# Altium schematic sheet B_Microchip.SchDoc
size B; CompanyName: Microchip Technology Inc.; Organization: Microchip Technology; Address1: 2355 West Chandler Blvd.; Address2: Chandler, AZ  85224; Address4: USA; DocumentNumber: 1; SheetNumber: 1; SheetTotal: 1; SheetTitle: 3p3V_SAM9X6_SDRAM_MIC23201
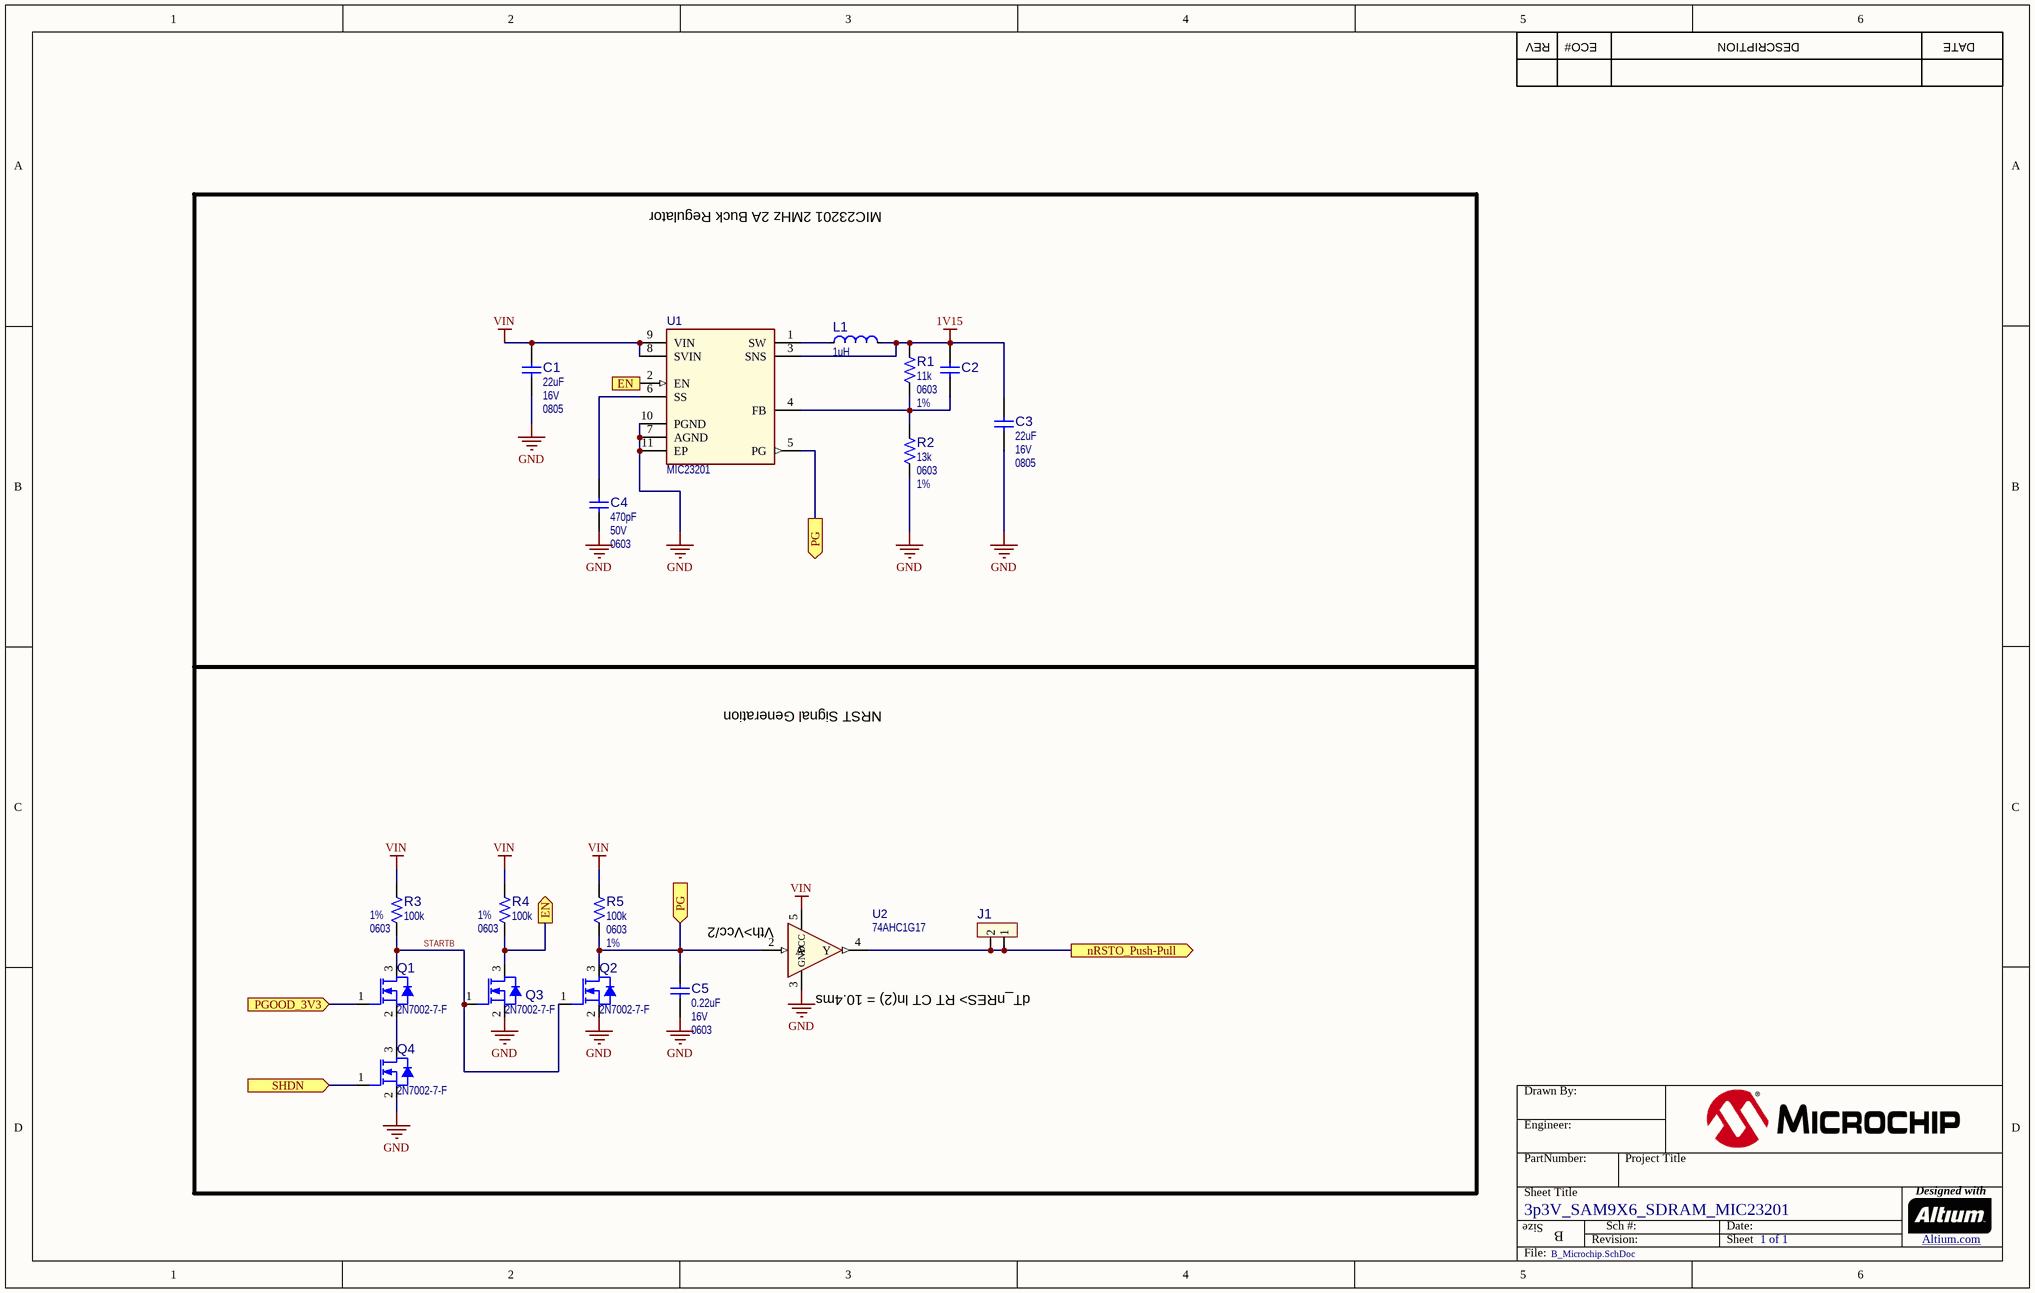
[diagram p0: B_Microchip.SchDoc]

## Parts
?  (no value)  (graphical)
C1  value 22uF  Voltage: 16V  Package: 0805  [CAP_C_0805]  (hidden comment: Capacitor NP)
C2  Capacitor NP  [CAP_C_0603]  (value not drawn)
C3  value 22uF  Voltage: 16V  Package: 0805  [CAP_C_0805]  (hidden comment: Capacitor NP)
C4  value 470pF  Voltage: 50V  Package: 0603  [CAP_C_0603]  (hidden comment: Capacitor NP)
C5  value 0.22uF  Voltage: 16V  Package: 0603  [CAP_C_0603]  (hidden comment: Capacitor NP)
J1  Header 1x2  [HDR_M_2.54_1x2]  (value not drawn)
L1  value 1uH  [IND_C_2520]  (hidden comment: Inductor)
Q1  value 2N7002-7-F  [SOT-23-3]  (hidden comment: Transistor MOS-N GSD)
Q2  value 2N7002-7-F  [SOT-23-3]  (hidden comment: Transistor MOS-N GSD)
Q3  value 2N7002-7-F  [SOT-23-3]  (hidden comment: Transistor MOS-N GSD)
Q4  value 2N7002-7-F  [SOT-23-3]  (hidden comment: Transistor MOS-N GSD)
R1  value 11k  Package: 0603  Tolerance: 1%  [RES_C_0603]  (hidden comment: Resistor)
R2  value 13k  Package: 0603  Tolerance: 1%  [RES_C_0603]  (hidden comment: Resistor)
R3  value 100k  Package: 0603  Tolerance: 1%  [RES_C_0603]  (hidden comment: Resistor)
R4  value 100k  Package: 0603  Tolerance: 1%  [RES_C_0603]  (hidden comment: Resistor)
R5  value 100k  Package: 0603  Tolerance: 1%  [RES_C_0603]  (hidden comment: Resistor)
U1  value MIC23201  [MLF-10_3x3_1.6X2.5]  (hidden comment: MIC23201 MLF-10)
U2  value 74AHC1G17  [SC-70-5]  (hidden comment: 74AHC1G17 TSSOP5)

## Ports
EN (in), EN (out), nRSTO_Push-Pull (out), PG (in), PG (out), PGOOD_3V3 (in), SHDN (in)

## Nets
1V15: C2.2 C3.2 L1.2(F) R1.2 U1.3(SNS)
GND: C1.1 C3.1 C4.1 C5.1 Q2.2(S) Q3.2(S) Q4.2(S) R2.1 U1.7(AGND) U1.10(PGND) U1.11(EP) U2.3(GND)
VIN: C1.2 R3.1 R4.1 R5.2 U1.8(SVIN) U1.9(VIN) U2.5(VCC)
EN: Q3.3(D) R4.2 U1.2(EN) ; port EN
nRSTO_Push-Pull: J1.1 J1.2 U2.4(Y) ; port nRSTO_Push-Pull
PG: C5.2 Q2.3(D) R5.1 U1.5(PG) U2.2(A) ; port PG
PGOOD_3V3: Q1.1(G) ; port PGOOD_3V3
SHDN: Q4.1(G) ; port SHDN
STARTB: Q1.3(D) Q2.1(G) Q3.1(G) R3.2
NetC2_1: C2.1 R1.1 R2.2 U1.4(FB)
NetC4_2: C4.2 U1.6(SS)
NetL1_1: L1.1(S) U1.1(SW)
NetQ1_2: Q1.2(S) Q4.3(D)

Not connected (* = marked no-connect by the designer): U2 1(NC)

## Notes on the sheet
- REV
- ECO#
- DESCRIPTION
- DATE
- MIC23201 2MHz 2A Buck Regulator
- NRST Signal Generation
- (near U2) Vth>Vcc/2
- (near U2) dT_nRES> RT CT ln(2) = 10.4ms

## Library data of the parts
? = Title Block B
C1 C3 = CAP0627: Capacitor; Manufacturer 1: TDK; Manufacturer Part Number 1: C2012X5R1C226K; Description_: CAP CER 22uF 16V 10% X5R SMD 0805; Dev Tools Status: Production; Tolerance: 10%; Temperature Coeffcient: X5R; Type: Ceramic; Populated: Yes
C2 = CAP0521: Capacitor; Manufacturer 1: Murata; Manufacturer Part Number 1: GRM1885C1H680JA01D; Value: 68pF; Voltage: 50V; Description_: CAP CER 68pF 50V 5% C0G SMD 0603; Dev Tools Status: Production; Tolerance: 5%; Temperature Coeffcient: C0G; Type: Ceramic; Populated: Yes
C4 = CAP0408: Capacitor; Manufacturer 1: Johanson Dielectrics; Manufacturer Part Number 1: 500R14W471KV4T; Description_: CAP CER 470pF 50V 10% X7R SMD 0603; Dev Tools Status: Production; Tolerance: 10%; Temperature Coeffcient: X7R; Type: Ceramic; Populated: Yes
C5 = CAP0191: Capacitor; Manufacturer 1: KEMET; Manufacturer Part Number 1: C0603C224Z4VACTU; Description_: CAP CER 0.22uF 16V 20% Y5V SMD 0603; Dev Tools Status: Production; Tolerance: 20%; Temperature Coeffcient: Y5V; Type: Ceramic; Populated: Yes
J1 = CON1108: Manufacturer 1: FCI; Manufacturer Part Number 1: 77311-118-02LF; Description_: CON HDR-2.54 Male 1x2 Gold 5.84MH TH VERT; Dev Tools Status: Production; Owner: Bogdan P (M91398); Populated: Yes
L1 = IND1326: Manufacturer 1: TDK; Manufacturer Part Number 1: MLP2520W1R0MT0S1; Description_: INDUCTOR 1uH 2.3A 20% SMD 2520; Dev Tools Status: Production; Owner: Razvan Cristescu; DCR: 0.062R; RMS Current: 2.3A; Test Frequency: 2MHz; Populated: YES
Q1-Q4 = TRA1102: Transistor MOS; Manufacturer 1: Diodes Inc; Description_: TRANS FET N-CH 2N7002-7-F 60V 170mA 370mW SOT-23-3; Dev Tools Status: Production; Type: FET; Current: 170mA; Drain to Source Voltage: 60V; Gate to Source Voltage: 20V; Power: 370mW; Owner: Adrian M (M91404); Populated: YES
R1 = RSMT0550: Manufacturer 1: Panasonic; Manufacturer Part Number 1: ERJ-3EKF1102V; Description_: RES TKF 11k 1% 1/10W SMD 0603; Dev Tools Status: Production; Voltage: 75V; Temperature Coeffcient: 100ppm/C; Power: 1/10W; Populated: Yes
R2 = RES1121: Manufacturer 1: Panasonic; Manufacturer Part Number 1: ERJ-3EKF1302V; Description_: RES TKF 13k 1% 1/10W SMD 0603; Dev Tools Status: Production; Voltage: 75V; Temperature Coeffcient: 100ppm/C; Power: 1/10W; Owner: Mihai T(M91442); Populated: Yes
R3-R5 = RES1066: Manufacturer 1: Vishay; Manufacturer Part Number 1: MCT06030C1003FP500; Description_: RES TF 100k 1% 1/8W SMD 0603; Dev Tools Status: Production; Voltage: 75V; Temperature Coeffcient: 50ppm/C; Power: 1/8W; Owner: Tad Ahlvers; Populated: Yes
U1 = MIC7256: Manufacturer 1: Microchip Technology; Manufacturer Part Number 1: MIC23201YML-TR; Description_: MCHP ANALOG SWITCHER Buck 0.95V to 3.6V 2A MIC23201YML-TR MLF-10; MAPS Description: 2MHz PWM 2A Buck Regulator with HSC; Dev Tools Status: Production; Owner: Sam Charles; MPC: 22830YJFAA02; LeadContent: Pb-FREE; PackingMedia: T/R; Stage: REL; LeadCount: 10; PackageWidth: 3x3x0.9mm; ForceMinOrderQtyMult: True; MinOrderQty: 1; TempRange: -40C to +125C; tblDeviceFamilyID: 7698; InputVoltageRangeMin: 2.7; InputVoltageRangeMax: 5.5; VoutMin: 0.62; VoutMax: 3.6; QuiescentCurrent: 1.15; SwitchingFrequency: 2000; Populated: YES
U2 = IC1595: Manufacturer 1: Nexperia USA Inc.; Manufacturer Part Number 1: 74AHC1G17GWH; MCHP-ID: IC1595; Description_: IC BUFFER Schmitt trigger 74AHC1G17GW GATE SGL CMOS SC-70-5; Dev Tools Status: Design; Vin: +2V to +5.5V; Owner: Cristian Papuc; Populated: YES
